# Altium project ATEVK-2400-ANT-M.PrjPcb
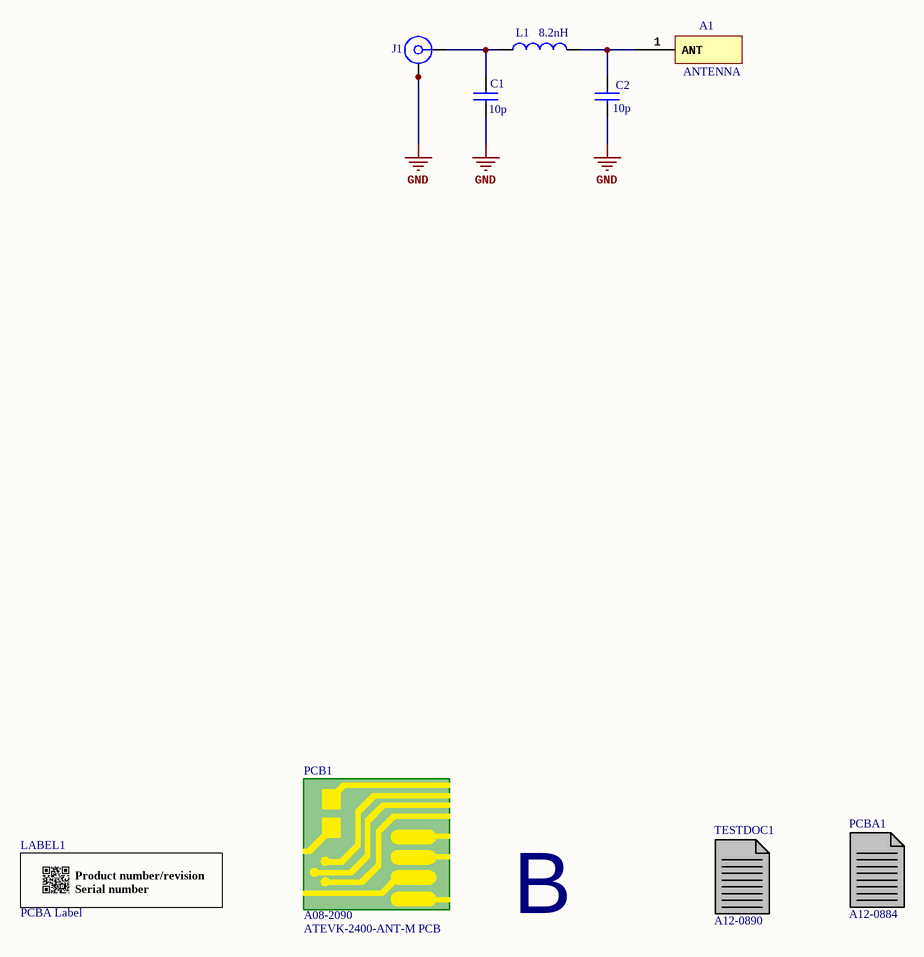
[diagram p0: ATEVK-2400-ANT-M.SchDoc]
1 sheet, 9 parts. Net scope: global (net labels, ports and power ports of the same name join across sheets).
Board file: ATEVK-2400-ANT-M.PcbDoc

## Sheet ATEVK-2400-ANT-M.SchDoc: ATEVK-900-ANT-M
size A3; Organization: ATMEL INDIA; Address1: CHENNAI; Address3: INDIA; Revision: 1; SheetNumber: 1; SheetTotal: 1; CheckedBy: SY; DrawnBy: OJS; PageSetup: Record=PageOptions¦CenterHorizontal=True¦CenterVertical=True¦PrintScale=0.73¦XCorrection=1.00¦YCorrection=1.00¦PrintKind=1¦BorderSize=5000000¦LeftOffset=0¦BottomOffset=0¦Orientation=2¦PaperLength=1000¦PaperWidth=1000¦Scale=100¦PaperSource=7¦PrintQuality=-4¦MediaType=1¦DitherType=10¦PaperKind=Letter¦PrintScaleMode=1

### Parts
A1  ANTENNA  (graphical)
C1  value 10p  [AP1-00038]  (hidden comment: CAP-NONPOL)
C2  value 10p  [AP1-00038]  (hidden comment: CAP-NONPOL)
J1  Board Edge Mounting  [AP8-00443]  (value not drawn)
L1  value 8.2nH  [AP1-00038]  (hidden comment: New part to be used in "ATEVK-2400-ANT-M")
LABEL1  value PCBA Label  [AP8-00317]  (hidden comment: PCBA_LABEL)
PCB1  value ATEVK-2400-ANT-M PCB  AN: A08-2090  (hidden comment: PCB)  (mechanical)
PCBA1  AN: A12-0884  (hidden comment: PCBA documentation)  (mechanical)
TESTDOC1  AN: A12-0890  (hidden comment: TESTDOC)  (mechanical)

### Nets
GND: C1.2 C2.2 J1.2 J1.2.1
NetA1_1: A1.1(ANT) C2.1 L1.2
NetC1_1: C1.1 J1.1 L1.1

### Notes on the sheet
- B

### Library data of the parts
C1 C2 = A01-0015: Ceramic capacitor, SMD 0402, NP0, 50V, +/-5%; PartGroup: Capacitors,Ceramic,SMD 0402; TemperatureRange: -55 - +125 deg C; ComponentStatus: 'Active (verified)'
J1 = A08-1047: End Launch Jack Receptacle, Round Contact (de21535); Manuf.Part#: 142-0711-821; Manufacturer: EMERSON; PartGroup: Mechanical devices,Connectors,Coaxial; Art.-Nr.: 21535; Value: 142-0711-821; ComponentStatus: 'Active (verified)'
L1 = A03-0193: RF Inductor, 8.2nH, +/-5%, 0.4Ohm, 250mA, 0402; PartGroup: Inductors,RF,SMD 0402; TemperatureRange: -40Â°C ~ 100Â°C; ComponentStatus: 'New (not verified)'
LABEL1 = A09-0611: PCBA identification label PP Top White Gloss; PartGroup: Mechanical devices,Packaging materials,Printed Labels; Manufacturer: ACT Logimark AS; MPN: 505462; ComponentStatus: 'Active (verified)'
PCB1 = A08-2090: ATEVK-2400-ANT-M PCB gerber; PartGroup: Mechanical devices,Printed circuit boards; ComponentStatus: 'New (not verified)'
PCBA1 = A12-0884: ATEVK-900-ANT-M PCBA Doc; PartGroup: Documentation,PCBA Documents,Atmel; Value: ATEVK-900-ANT-M PCBA document; ComponentStatus: 'Active (verified)'
TESTDOC1 = A12-0890: 900MHz PCB Antenna Production test instructions; PartGroup: Documentation,Procedures,Test Instructions; ComponentStatus: 'Active (verified)'

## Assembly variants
Variant of ATEVK-2400-ANT-M: not fitted C1 C2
